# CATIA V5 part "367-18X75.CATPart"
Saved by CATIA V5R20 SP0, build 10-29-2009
Part number: 367-18X75
Definition: NONE
Nomenclature: 367-18X75
Source: Unknown
Description: 367-18X75
Bounding box of the stored display mesh (mm): x 0 to 75, y -14 to 14, z -14 to 14
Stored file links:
  C:\Users\Utente\Desktop\IO LAVORO\3D X SITO CF\X SITO\PLASTICA\3D files 367\367-18X75.CATPart
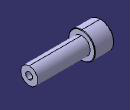
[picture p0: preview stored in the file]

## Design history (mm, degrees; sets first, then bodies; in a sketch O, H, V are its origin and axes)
Body1 "367-18X75" (main body)
  Solid1: solid without history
